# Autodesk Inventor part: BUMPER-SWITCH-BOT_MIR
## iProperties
Created: 2007-08
Part Number: BUMPER-SWITCH-BOT_MIR
Material: ABS Plastic
Document SubType Name: Modeling
Density: 1.06 g/cm^3
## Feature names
1. Derived Body1 [Tagging]
